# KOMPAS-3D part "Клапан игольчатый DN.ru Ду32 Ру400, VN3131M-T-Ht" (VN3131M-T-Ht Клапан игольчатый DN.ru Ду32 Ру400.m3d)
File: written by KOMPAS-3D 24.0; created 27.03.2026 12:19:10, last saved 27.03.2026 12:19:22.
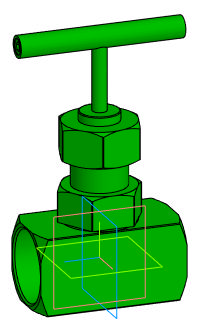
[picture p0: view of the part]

Document properties: Автор: Илья; Полное имя файла: D:\Обмен\Заказы с фриланса\DN.ru\VNxxM-T-Ht Клапан игольчатый DN.ru Ду8-50 Ру400\VN3131M-T-Ht Клапан игольчатый DN.ru Ду8-50 Ру400\DN32\VN3131M-T-Ht Клапан игольчатый DN.ru Ду32 Ру400.m3d

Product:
- Body: Body10  | qty 1
    Масса: 1.287778
- Part/product: Клапан игольчатый DN.ru Ду32 Ру400  | designation VN3131M-T-Ht
    Масса: 1
    Раздел спецификации: Прочие изделия
    Примечание: D090-02134

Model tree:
1. Body10  (labels: Body10)

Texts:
  VN3131M-T-Ht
